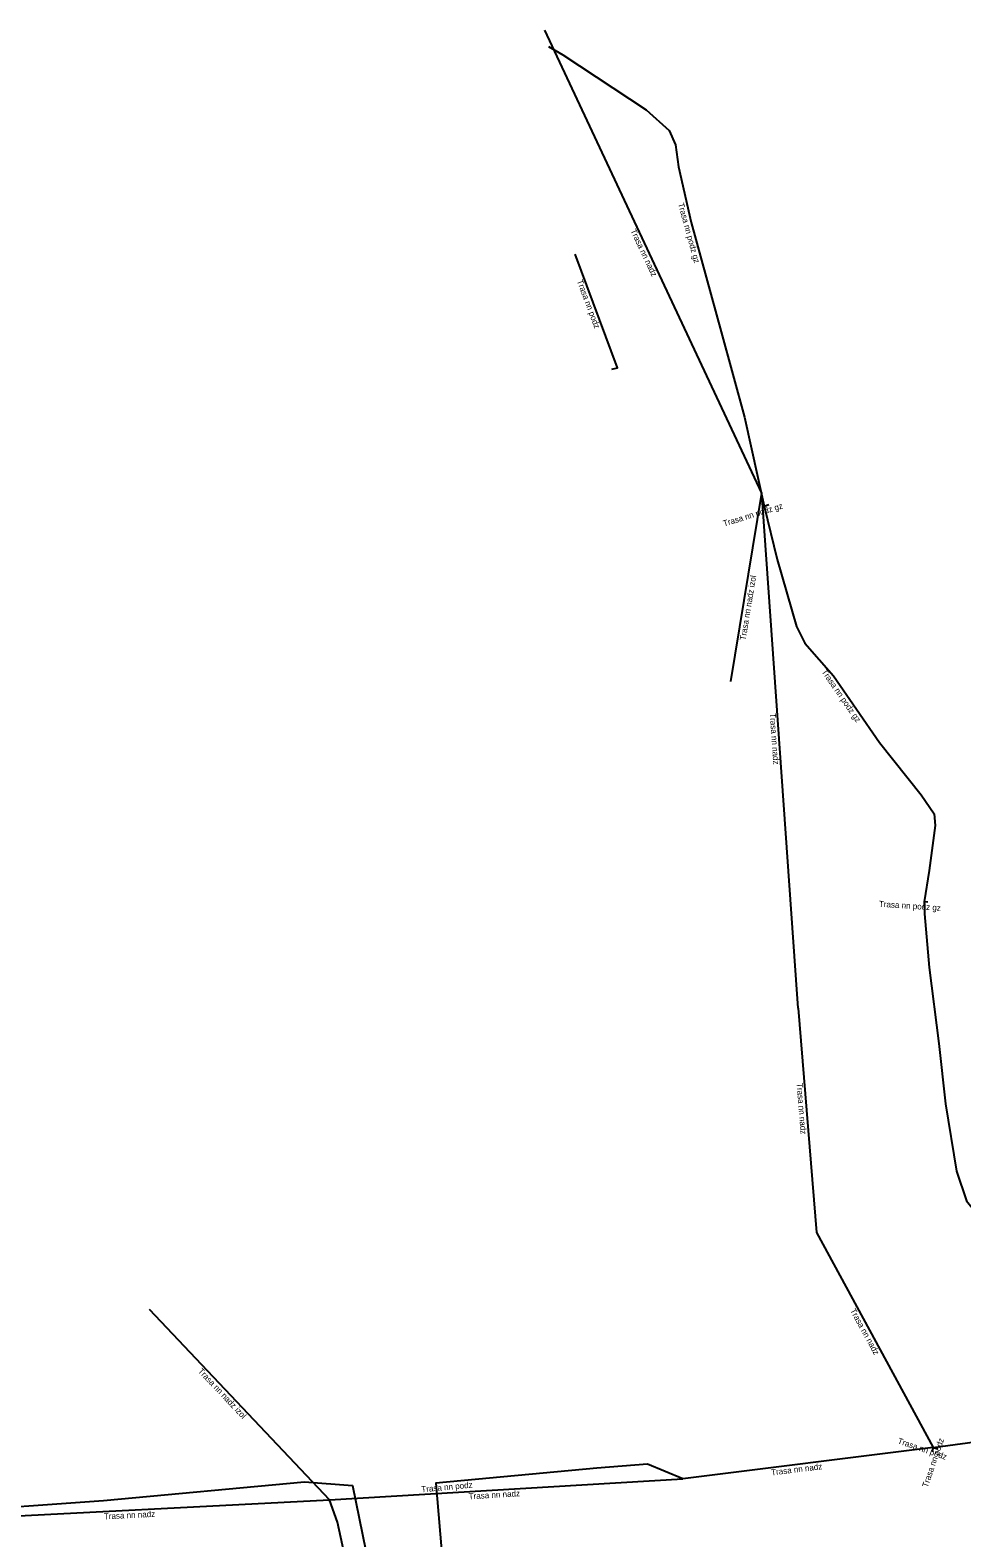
# Model space of a CAD drawing. Extents: x -682605 to -681812, y -1059958 to -1059650.
# Drawn here: x -682252.8 to -682175.3, y -1059800.1 to -1059674.7 of the extents above; entities that cross this region are included whole.
import ezdxf

# ---------------------------------------------------------------- set-up
doc = ezdxf.new("R2010")
doc.units = 0
for name, color, linetype in [('Popiskový text - Ostatní atributy Trasy', 7, 'Continuous'), ('Spojnice NN', 7, 'Continuous'), ('Spojnice VN', 7, 'Continuous')]:
    doc.layers.add(name, color=color, linetype=linetype)

msp = doc.modelspace()

# ---------------------------------------------------------------- linework, layer by layer
at = {"layer": 'Spojnice NN'}
for points in [[(-682191.92, -1059713.17), (-682209.99, -1059674.67)], [(-682209.68, -1059676.04), (-682208.5, -1059676.73), (-682201.56, -1059681.29), (-682199.64, -1059683.02), (-682199.1, -1059684.22), (-682198.86, -1059686.03), (-682197.81, -1059690.68), (-682195.32, -1059699.76), (-682193.36, -1059706.86), (-682191.74, -1059714.25)], [(-682204.41, -1059702.88), (-682203.93, -1059702.77), (-682207.47, -1059693.29)], [(-682194.5, -1059728.84), (-682191.92, -1059713.17)], [(-682188.9, -1059756.02), (-682191.92, -1059713.17)], [(-682191.74, -1059714.25), (-682191.35, -1059714.13)], [(-682191.74, -1059714.25), (-682190.66, -1059718.7), (-682189.04, -1059724.27), (-682188.36, -1059725.65), (-682185.97, -1059728.38), (-682182.14, -1059733.93), (-682178.68, -1059738.27), (-682177.6, -1059739.84), (-682177.5, -1059740.81), (-682178.01, -1059744.56), (-682178.42, -1059747.18)], [(-682178.42, -1059747.18), (-682178.39, -1059748.18), (-682178.01, -1059752.62), (-682177.2, -1059758.95), (-682176.65, -1059763.97), (-682175.73, -1059769.58), (-682174.89, -1059772.03), (-682173.5, -1059773.75), (-682171.15, -1059775.71), (-682169.39, -1059776.63), (-682168.15, -1059778.96), (-682167.07, -1059788.54), (-682166.66, -1059789.52), (-682161.75, -1059789.13), (-682156.53, -1059788.56), (-682149.95, -1059787.87), (-682144.97, -1059787.26), (-682140.54, -1059786.75), (-682136.66, -1059786.25), (-682133.27, -1059785.87), (-682129.42, -1059785.53), (-682123.44, -1059784.44)], [(-682178.12, -1059747.2), (-682178.42, -1059747.18)], [(-682188.9, -1059756.02), (-682187.38, -1059774.68)], [(-682187.38, -1059774.68), (-682177.66, -1059792.56)], [(-682242.9, -1059781.06), (-682227.92, -1059796.92)], [(-682177.66, -1059792.56), (-682144.43, -1059788.05)], [(-682177.66, -1059792.56), (-682198.49, -1059795.15)], [(-682177.66, -1059792.56), (-682177.78, -1059792.91)], [(-682177.66, -1059792.56), (-682177.29, -1059792.68)], [(-682198.49, -1059795.15), (-682201.43, -1059793.93), (-682205.66, -1059794.29), (-682219.07, -1059795.53), (-682218.47, -1059802.37), (-682217.62, -1059812.54)], [(-682227.92, -1059796.92), (-682198.49, -1059795.15)], [(-682259.21, -1059798.53), (-682227.92, -1059796.92)], [(-682225.15, -1059833.77), (-682225.07, -1059824.75), (-682225.91, -1059808.55), (-682226.35, -1059802.85), (-682227.25, -1059798.78), (-682227.92, -1059796.92)]]:
    msp.add_lwpolyline(points, dxfattribs=at)
at = {"layer": 'Spojnice VN'}
msp.add_lwpolyline([(-682419.71, -1059843.18), (-682409.04, -1059841.86), (-682401.8, -1059840.66), (-682391.43, -1059837.47), (-682378.96, -1059833.37), (-682366.87, -1059827.88), (-682350.77, -1059821.14), (-682334.98, -1059814.51), (-682322.31, -1059809.45), (-682316.78, -1059807.47), (-682307.06, -1059804.21), (-682298.09, -1059802), (-682285.23, -1059800.25), (-682273.9, -1059799.1), (-682259.98, -1059797.91), (-682246.72, -1059796.96), (-682230, -1059795.42), (-682225.98, -1059795.71), (-682224.89, -1059801.14), (-682222.94, -1059818.12), (-682221.47, -1059834.28)], dxfattribs=at)

# ---------------------------------------------------------------- texts
at = {"layer": 'Popiskový text - Ostatní atributy Trasy'}
for s, rotation, p in [('Trasa nn podz gz', 285.3352, (-682198.91, -1059689.11)), ('Trasa nn nadz', 295.1469, (-682202.88, -1059691.35)), ('Trasa nn podz', 290.479, (-682207.33, -1059695.53)), ('Trasa nn podz gz', 17.1027, (-682195.07, -1059715.96)), ('Trasa nn nadz izol', 80.632, (-682193.28, -1059725.45)), ('Trasa nn podz gz', 304.6092, (-682186.99, -1059728.04)), ('Trasa nn nadz', 274.032, (-682191.27, -1059731.5)), ('Trasa nn podz gz', 356.1859, (-682182.2, -1059747.58)), ('Trasa nn nadz', 274.6322, (-682189.04, -1059762.26)), ('Trasa nn nadz', 298.5311, (-682184.6, -1059781.16)), ('Trasa nn nadz izol', 313.356, (-682238.89, -1059786.24)), ('Trasa nn podz', 341.0556, (-682180.67, -1059792.21)), ('Trasa nn podz', 71.1255, (-682178.13, -1059795.92)), ('Trasa nn nadz', 7.1, (-682191.12, -1059794.89)), ('Trasa nn podz', 5.283, (-682220.24, -1059796.29)), ('Trasa nn nadz', 3.4418, (-682216.31, -1059796.87)), ('Trasa nn nadz', 2.9455, (-682246.67, -1059798.54))]:
    msp.add_text(s, height=0.5, rotation=rotation, dxfattribs=at).set_placement(p)

doc.saveas('drawing.dxf')
